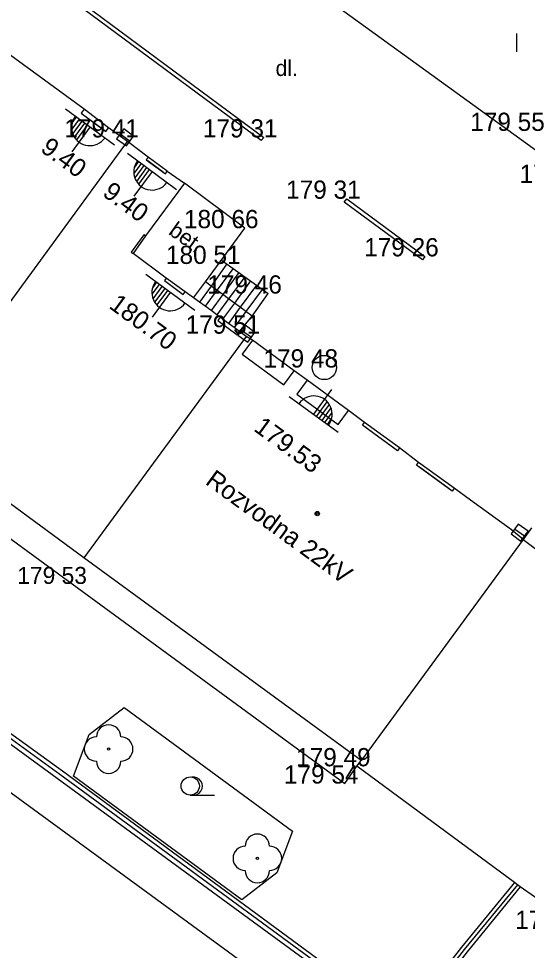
# Model space of a CAD drawing. Extents: x -537755 to -537431, y -1180722 to -1180510.
# Drawn here: x -537525.89 to -537504.97, y -1180651.27 to -1180612.95 of the extents above; entities that cross this region are included whole.
import ezdxf

# ---------------------------------------------------------------- set-up
doc = ezdxf.new("R2010")
doc.units = 0
for name, color, linetype in [('Vrstva 1', 7, 'Continuous'), ('Vrstva 10', 7, 'Continuous'), ('Vrstva 11', 7, 'Continuous'), ('Vrstva 21', 7, 'Continuous'), ('Vrstva 22', 7, 'Continuous'), ('Vrstva 27', 7, 'Continuous'), ('Vrstva 3', 7, 'Continuous'), ('Vrstva 36', 7, 'Continuous'), ('Vrstva 37', 7, 'Continuous'), ('Vrstva 39', 7, 'Continuous'), ('Vrstva 4', 7, 'Continuous'), ('Vrstva 40', 7, 'Continuous'), ('Vrstva 41', 7, 'Continuous'), ('Vrstva 5', 7, 'Continuous'), ('Vrstva 6', 7, 'Continuous'), ('Vrstva 7', 7, 'Continuous'), ('Vrstva 9', 7, 'Continuous')]:
    doc.layers.add(name, color=color, linetype=linetype)

msp = doc.modelspace()

# ---------------------------------------------------------------- linework, layer by layer
at = {"layer": 'Vrstva 1'}
for p, q in [((-537523.2, -1180616.68), (-537523.2, -1180616.68)), ((-537522.35, -1180617.55), (-537522.35, -1180617.55)), ((-537522.19, -1180617.44), (-537522.19, -1180617.44)), ((-537521.51, -1180617.84), (-537521.51, -1180617.84)), ((-537515.91, -1180617.97), (-537515.91, -1180617.97)), ((-537515.81, -1180617.84), (-537515.81, -1180617.84)), ((-537520.56, -1180618.65), (-537520.56, -1180618.65)), ((-537519.93, -1180619.28), (-537519.93, -1180619.28)), ((-537519.78, -1180619.23), (-537519.78, -1180619.23)), ((-537519.07, -1180619.72), (-537519.07, -1180619.72)), ((-537512.39, -1180620.36), (-537512.39, -1180620.36)), ((-537516.59, -1180621.57), (-537516.59, -1180621.57)), ((-537520.67, -1180621.89), (-537520.67, -1180621.89)), ((-537521.18, -1180622.61), (-537521.18, -1180622.61)), ((-537509.18, -1180622.73), (-537509.18, -1180622.73)), ((-537517.33, -1180623.04), (-537517.33, -1180623.04)), ((-537519.82, -1180623.62), (-537519.82, -1180623.62)), ((-537519.04, -1180624.19), (-537519.04, -1180624.19)), ((-537515.63, -1180624.26), (-537515.63, -1180624.26)), ((-537517.6, -1180625.23), (-537517.6, -1180625.23)), ((-537516.28, -1180625.19), (-537516.28, -1180625.19)), ((-537516.8, -1180625.82), (-537516.8, -1180625.82)), ((-537516.52, -1180625.91), (-537516.52, -1180625.91)), ((-537516.27, -1180626.18), (-537516.27, -1180626.18)), ((-537514.56, -1180627.44), (-537514.56, -1180627.44)), ((-537513.32, -1180627.3), (-537513.32, -1180627.3)), ((-537514.03, -1180627.82), (-537514.03, -1180627.82)), ((-537512.33, -1180629.07), (-537512.33, -1180629.07)), ((-537511.66, -1180629.56), (-537511.66, -1180629.56)), ((-537511.64, -1180629.75), (-537511.64, -1180629.75)), ((-537510.23, -1180630.61), (-537510.23, -1180630.61)), ((-537509.44, -1180631.2), (-537509.44, -1180631.2)), ((-537508.19, -1180632.29), (-537508.19, -1180632.29)), ((-537507.98, -1180632.26), (-537507.98, -1180632.26)), ((-537507.31, -1180632.75), (-537507.31, -1180632.75)), ((-537505.62, -1180633.97), (-537505.62, -1180633.97)), ((-537505.29, -1180634.09), (-537505.29, -1180634.09)), ((-537523.61, -1180636.2), (-537523.61, -1180636.2)), ((-537511.94, -1180643.67), (-537511.94, -1180643.67)), ((-537524.09, -1180643.89), (-537524.09, -1180643.89)), ((-537511.98, -1180643.7), (-537511.98, -1180643.7)), ((-537512.48, -1180644.41), (-537512.48, -1180644.41)), ((-537505.26, -1180648.66), (-537505.26, -1180648.66))]:
    msp.add_line(p, q, dxfattribs=at)
at = {"layer": 'Vrstva 10'}
for p, q in [((-537502.79, -1180619.71), (-537517.675, -1180608.917)), ((-537528.74, -1180642.94), (-537511.18, -1180655.77))]:
    msp.add_line(p, q, dxfattribs=at)
at = {"layer": 'Vrstva 11'}
for p, q in [((-537515.91, -1180617.97), (-537530.007, -1180607.535)), ((-537529.9, -1180607.39), (-537515.81, -1180617.84)), ((-537515.81, -1180617.84), (-537515.91, -1180617.97)), ((-537531.72, -1180630.31), (-537512.48, -1180644.41)), ((-537512.48, -1180644.41), (-537511.98, -1180643.7))]:
    msp.add_line(p, q, dxfattribs=at)
for points in [[(-537518.692, -1180624.435), (-537518.208, -1180623.776), (-537516.59, -1180621.57), (-537519.07, -1180619.72)], [(-537512.497, -1180620.505), (-537512.39, -1180620.36), (-537509.18, -1180622.73), (-537509.287, -1180622.875), (-537512.497, -1180620.505)], [(-537517.33, -1180623.04), (-537517.971, -1180623.95), (-537518.455, -1180624.609)], [(-537517.073, -1180623.224), (-537517.733, -1180624.124), (-537518.217, -1180624.784)], [(-537516.832, -1180623.397), (-537517.494, -1180624.299), (-537517.978, -1180624.959)], [(-537516.592, -1180623.57), (-537517.255, -1180624.474), (-537517.739, -1180625.134)], [(-537516.351, -1180623.742), (-537517.017, -1180624.649), (-537517.501, -1180625.309)], [(-537516.8, -1180625.82), (-537516.28, -1180625.19), (-537516.539, -1180624.999), (-537516.778, -1180624.824), (-537517.017, -1180624.649), (-537517.255, -1180624.474), (-537517.494, -1180624.299), (-537517.733, -1180624.124), (-537517.971, -1180623.95), (-537518.208, -1180623.776)], [(-537516.111, -1180623.915), (-537516.778, -1180624.824), (-537517.262, -1180625.484)], [(-537515.87, -1180624.087), (-537516.539, -1180624.999), (-537517.023, -1180625.659)], [(-537516.28, -1180625.19), (-537515.63, -1180624.26)]]:
    msp.add_lwpolyline(points, dxfattribs=at)
at = {"layer": 'Vrstva 21'}
for p, q in [((-537521.555, -1180641.285), (-537514.633, -1180646.374)), ((-537516.706, -1180649.194), (-537523.628, -1180644.106))]:
    msp.add_line(p, q, dxfattribs=at)
for points in [[(-537523.628, -1180644.106), (-537522.994, -1180642.399), (-537521.555, -1180641.285)], [(-537514.633, -1180646.374), (-537515.267, -1180648.08), (-537516.706, -1180649.194)]]:
    msp.add_lwpolyline(points, dxfattribs=at)
at = {"layer": 'Vrstva 22'}
for centre in [(-537522.189, -1180642.992), (-537516.072, -1180647.488)]:
    msp.add_circle(centre, 0.05, dxfattribs=at)
for centre, start, end in [((-537522.189, -1180642.492), 0, 180), ((-537522.689, -1180642.992), 90, 270), ((-537521.689, -1180642.992), 270, 90), ((-537522.189, -1180643.492), 180, 0), ((-537516.072, -1180646.988), 0, 180), ((-537516.572, -1180647.488), 90, 270), ((-537515.572, -1180647.488), 270, 90), ((-537516.072, -1180647.988), 180, 0)]:
    msp.add_arc(centre, 0.5, start, end, dxfattribs=at)
at = {"layer": 'Vrstva 27'}
for p, q in [((-537521.712, -1180617.693), (-537521.308, -1180617.987)), ((-537516.722, -1180625.763), (-537516.318, -1180626.057)), ((-537505.088, -1180634.237), (-537505.492, -1180633.943))]:
    msp.add_line(p, q, dxfattribs=at)
for points in [[(-537521.859, -1180617.895), (-537521.455, -1180618.189), (-537521.161, -1180617.785), (-537521.565, -1180617.491)], [(-537516.869, -1180625.965), (-537516.465, -1180626.259), (-537516.171, -1180625.855), (-537516.575, -1180625.561)], [(-537504.941, -1180634.035), (-537505.345, -1180633.741), (-537505.639, -1180634.145), (-537505.235, -1180634.439)]]:
    msp.add_lwpolyline(points, close=True, dxfattribs=at)
msp.add_circle((-537513.32, -1180627.3), 0.5, dxfattribs=at)
at = {"layer": 'Vrstva 36'}
for p, q in [((-537505.406, -1180614.312), (-537505.406, -1180613.562)), ((-537518.832, -1180644.888), (-537517.832, -1180644.888))]:
    msp.add_line(p, q, dxfattribs=at)
msp.add_circle((-537518.832, -1180644.513), 0.375, dxfattribs=at)
msp.add_arc((-537518.707, -1180644.513), 0.375, 260.4059, 99.5941, dxfattribs=at)
at = {"layer": 'Vrstva 37'}
for p, q in [((-537521.947, -1180618.159), (-537523.961, -1180616.677)), ((-537523.405, -1180617.086), (-537523.706, -1180617.494)), ((-537523.518, -1180617.003), (-537523.683, -1180617.227)), ((-537523.292, -1180617.169), (-537523.666, -1180617.676)), ((-537522.954, -1180617.418), (-537523.7, -1180618.431)), ((-537523.179, -1180617.252), (-537523.597, -1180617.819)), ((-537523.067, -1180617.335), (-537523.508, -1180617.935)), ((-537519.394, -1180619.987), (-537521.408, -1180618.505)), ((-537520.852, -1180618.914), (-537521.153, -1180619.322)), ((-537520.965, -1180618.831), (-537521.13, -1180619.055)), ((-537520.739, -1180618.997), (-537521.113, -1180619.504)), ((-537520.626, -1180619.08), (-537521.044, -1180619.647)), ((-537520.514, -1180619.163), (-537520.955, -1180619.763)), ((-537520.401, -1180619.246), (-537521.147, -1180620.259)), ((-537518.649, -1180624.952), (-537520.663, -1180623.472)), ((-537520.107, -1180623.88), (-537520.408, -1180624.289)), ((-537520.22, -1180623.797), (-537520.385, -1180624.021)), ((-537519.994, -1180623.963), (-537520.368, -1180624.471)), ((-537519.882, -1180624.046), (-537520.299, -1180624.613)), ((-537519.769, -1180624.129), (-537520.21, -1180624.729)), ((-537519.656, -1180624.212), (-537520.401, -1180625.226)), ((-537513.752, -1180629.225), (-537513.008, -1180628.211)), ((-537514.76, -1180628.486), (-537512.744, -1180629.964)), ((-537513.639, -1180629.308), (-537513.199, -1180628.707)), ((-537513.526, -1180629.391), (-537513.11, -1180628.823)), ((-537513.413, -1180629.473), (-537513.041, -1180628.965)), ((-537513.3, -1180629.556), (-537513.001, -1180629.147)), ((-537513.187, -1180629.639), (-537513.023, -1180629.415))]:
    msp.add_line(p, q, dxfattribs=at)
for centre, start, end in [((-537522.959, -1180617.425), 143.0142, 324.2603), ((-537520.406, -1180619.253), 143.0142, 324.2603), ((-537519.661, -1180624.219), 143.053, 324.299), ((-537513.747, -1180629.218), 323.1261, 144.3721)]:
    msp.add_arc(centre, 0.75, start, end, dxfattribs=at)
at = {"layer": 'Vrstva 39'}
for radius in [0.09, 0.0398]:
    msp.add_circle((-537513.608, -1180633.309), radius, dxfattribs=at)
at = {"layer": 'Vrstva 5'}
for p, q in [((-537523.2, -1180616.68), (-537531.89, -1180610.31)), ((-537523.2, -1180616.68), (-537523.317, -1180616.84)), ((-537523.317, -1180616.84), (-537522.298, -1180617.588)), ((-537522.19, -1180617.44), (-537523.2, -1180616.68)), ((-537522.298, -1180617.588), (-537522.19, -1180617.44)), ((-537521.415, -1180617.999), (-537522.19, -1180617.44)), ((-537529.001, -1180628.392), (-537521.415, -1180617.999)), ((-537520.56, -1180618.65), (-537521.415, -1180617.999)), ((-537520.56, -1180618.65), (-537520.64, -1180618.759)), ((-537520.64, -1180618.759), (-537519.856, -1180619.334)), ((-537519.78, -1180619.23), (-537520.56, -1180618.65)), ((-537519.856, -1180619.334), (-537519.78, -1180619.23)), ((-537519.78, -1180619.23), (-537519.07, -1180619.72)), ((-537519.07, -1180619.72), (-537520.67, -1180621.89)), ((-537520.741, -1180621.838), (-537521.261, -1180622.551)), ((-537520.67, -1180621.89), (-537520.741, -1180621.838)), ((-537520.67, -1180621.89), (-537521.18, -1180622.61)), ((-537521.261, -1180622.551), (-537521.18, -1180622.61)), ((-537519.82, -1180623.62), (-537521.18, -1180622.61)), ((-537519.82, -1180623.62), (-537519.897, -1180623.725)), ((-537519.897, -1180623.725), (-537519.118, -1180624.296)), ((-537519.04, -1180624.19), (-537519.82, -1180623.62)), ((-537519.118, -1180624.296), (-537519.04, -1180624.19)), ((-537518.692, -1180624.435), (-537519.04, -1180624.19)), ((-537518.455, -1180624.609), (-537518.692, -1180624.435)), ((-537518.217, -1180624.784), (-537518.455, -1180624.609)), ((-537517.978, -1180624.959), (-537518.217, -1180624.784)), ((-537517.739, -1180625.134), (-537517.978, -1180624.959)), ((-537517.6, -1180625.23), (-537517.739, -1180625.134)), ((-537517.6, -1180625.23), (-537517.703, -1180625.371)), ((-537517.501, -1180625.309), (-537517.6, -1180625.23)), ((-537517.703, -1180625.371), (-537516.902, -1180625.959)), ((-537517.262, -1180625.484), (-537517.501, -1180625.309)), ((-537517.023, -1180625.659), (-537517.262, -1180625.484)), ((-537516.8, -1180625.82), (-537517.023, -1180625.659)), ((-537516.528, -1180626.022), (-537523.205, -1180635.125)), ((-537516.902, -1180625.959), (-537516.8, -1180625.82)), ((-537516.528, -1180626.022), (-537516.8, -1180625.82)), ((-537516.27, -1180626.18), (-537516.528, -1180626.022)), ((-537516.27, -1180626.18), (-537516.693, -1180626.757)), ((-537514.56, -1180627.44), (-537516.27, -1180626.18)), ((-537516.693, -1180626.757), (-537514.981, -1180628.013)), ((-537514.981, -1180628.013), (-537514.56, -1180627.44)), ((-537514.03, -1180627.82), (-537514.56, -1180627.44)), ((-537514.03, -1180627.82), (-537514.455, -1180628.399)), ((-537512.33, -1180629.07), (-537514.03, -1180627.82)), ((-537512.753, -1180629.647), (-537512.33, -1180629.07)), ((-537511.66, -1180629.56), (-537512.33, -1180629.07)), ((-537511.744, -1180629.674), (-537511.66, -1180629.56)), ((-537510.313, -1180630.723), (-537511.744, -1180629.674)), ((-537510.23, -1180630.61), (-537511.66, -1180629.56)), ((-537523.205, -1180635.125), (-537530.19, -1180630.02)), ((-537510.23, -1180630.61), (-537510.313, -1180630.723)), ((-537509.44, -1180631.2), (-537510.23, -1180630.61)), ((-537509.523, -1180631.313), (-537509.44, -1180631.2)), ((-537508.068, -1180632.38), (-537509.523, -1180631.313)), ((-537507.98, -1180632.26), (-537509.44, -1180631.2)), ((-537507.98, -1180632.26), (-537508.068, -1180632.38)), ((-537507.31, -1180632.75), (-537507.98, -1180632.26)), ((-537505.139, -1180634.376), (-537505.62, -1180633.97)), ((-537504.8, -1180633.89), (-537505.139, -1180634.376)), ((-537505.139, -1180634.376), (-537511.796, -1180643.448)), ((-537505.139, -1180634.376), (-537498.531, -1180639.357)), ((-537511.803, -1180643.458), (-537523.205, -1180635.125)), ((-537511.98, -1180643.7), (-537511.803, -1180643.458)), ((-537511.796, -1180643.448), (-537511.803, -1180643.458)), ((-537502.765, -1180650.427), (-537505.26, -1180648.66))]:
    msp.add_line(p, q, dxfattribs=at)
for points in [[(-537505.502, -1180648.481), (-537511.98, -1180643.7)], [(-537505.381, -1180648.57), (-537505.502, -1180648.481)], [(-537505.26, -1180648.66), (-537505.381, -1180648.57)]]:
    msp.add_lwpolyline(points, dxfattribs=at)
at = {"layer": 'Vrstva 6'}
for p, q in [((-537523.261, -1180616.881), (-537522.35, -1180617.55)), ((-537519.93, -1180619.28), (-537520.575, -1180618.807)), ((-537520.741, -1180621.838), (-537521.261, -1180622.551)), ((-537519.897, -1180623.725), (-537519.118, -1180624.296)), ((-537517.703, -1180625.371), (-537516.902, -1180625.959)), ((-537516.693, -1180626.757), (-537514.981, -1180628.013)), ((-537514.455, -1180628.399), (-537512.753, -1180629.647)), ((-537510.42, -1180630.645), (-537511.64, -1180629.75)), ((-537508.19, -1180632.29), (-537509.404, -1180631.4)), ((-537505.62, -1180633.97), (-537507.31, -1180632.75))]:
    msp.add_line(p, q, dxfattribs=at)
at = {"layer": 'Vrstva 7'}
for p, q in [((-537541.09, -1180632), (-537524.304, -1180644.183)), ((-537524.197, -1180644.036), (-537540.848, -1180631.951)), ((-537540.61, -1180631.9), (-537524.09, -1180643.89)), ((-537510.043, -1180654.415), (-537524.197, -1180644.036)), ((-537524.09, -1180643.89), (-537510.065, -1180654.2)), ((-537524.304, -1180644.183), (-537510.233, -1180654.475))]:
    msp.add_line(p, q, dxfattribs=at)
for points in [[(-537505.502, -1180648.481), (-537507.684, -1180651.143), (-537510.065, -1180654.2)], [(-537505.381, -1180648.57), (-537507.567, -1180651.236), (-537510.043, -1180654.415)], [(-537505.26, -1180648.66), (-537507.45, -1180651.33), (-537509.973, -1180654.595), (-537510.02, -1180654.63)]]:
    msp.add_lwpolyline(points, dxfattribs=at)
at = {"layer": 'Vrstva 9'}
msp.add_line((-537517.552, -1180622.881), (-537515.63, -1180624.26), dxfattribs=at)

# ---------------------------------------------------------------- texts
at = {"layer": 'Vrstva 3'}
for s, height, p in [('179 55 ', 0.75, (-537507.32, -1180617.57)), ('179 41 ', 0.75, (-537524.01, -1180617.84)), ('179 31 ', 0.75, (-537518.31, -1180617.84)), ('179 43 ', 0.75, (-537505.29, -1180619.71)), ('179 31 ', 0.75, (-537514.89, -1180620.36)), ('180 66 ', 0.75, (-537519.09, -1180621.57)), ('179 26 ', 0.75, (-537511.68, -1180622.73)), ('180 51 ', 0.75, (-537519.83, -1180623.04)), ('179 46 ', 0.75, (-537518.13, -1180624.26)), ('179 51 ', 0.75, (-537519.02, -1180625.91)), ('179 48 ', 0.75, (-537515.82, -1180627.3)), ('179 53 ', 0.7, (-537525.943, -1180636.2)), ('179 54 ', 0.75, (-537514.98, -1180644.41)), ('179 49 ', 0.75, (-537505.47, -1180650.39))]:
    msp.add_text(s, height=height, dxfattribs=at).set_placement(p)
at = {"layer": 'Vrstva 37'}
for s, rotation, p in [('9.40', 323.721, (-537525.033, -1180618.383)), ('9.40', 323.721, (-537522.48, -1180620.211)), ('180.70', 323.7387, (-537522.215, -1180624.825)), ('179.53', 323.7387, (-537516.26, -1180629.875))]:
    msp.add_text(s, height=0.75, rotation=rotation, dxfattribs=at).set_placement(p)
at = {"layer": 'Vrstva 4'}
msp.add_text('179 49 ', height=0.75, dxfattribs=at).set_placement((-537514.48, -1180643.7))
at = {"layer": 'Vrstva 40'}
msp.add_text('dl.', height=0.65, dxfattribs=at).set_placement((-537515.323, -1180615.311))
msp.add_text('bet.', height=0.65, rotation=324.5543, dxfattribs=at).set_placement((-537519.765, -1180621.792))
at = {"layer": 'Vrstva 41'}
msp.add_text('Rozvodna 22kV', height=0.75, rotation=323.8395, dxfattribs=at).set_placement((-537518.251, -1180632.065))

doc.saveas('drawing.dxf')
